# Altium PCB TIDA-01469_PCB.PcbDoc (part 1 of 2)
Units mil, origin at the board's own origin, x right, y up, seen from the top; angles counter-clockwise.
Board outline 2303.15 x 3751.97 mil, 4 copper layers (Layer 1 - Top Layer, Layer 2 - GND, Layer 3 - PWR, Layer 4 - Bottom Layer), stack 61.634 mil thick; 66 components, 33 nets, 183 pads, 184 vias.
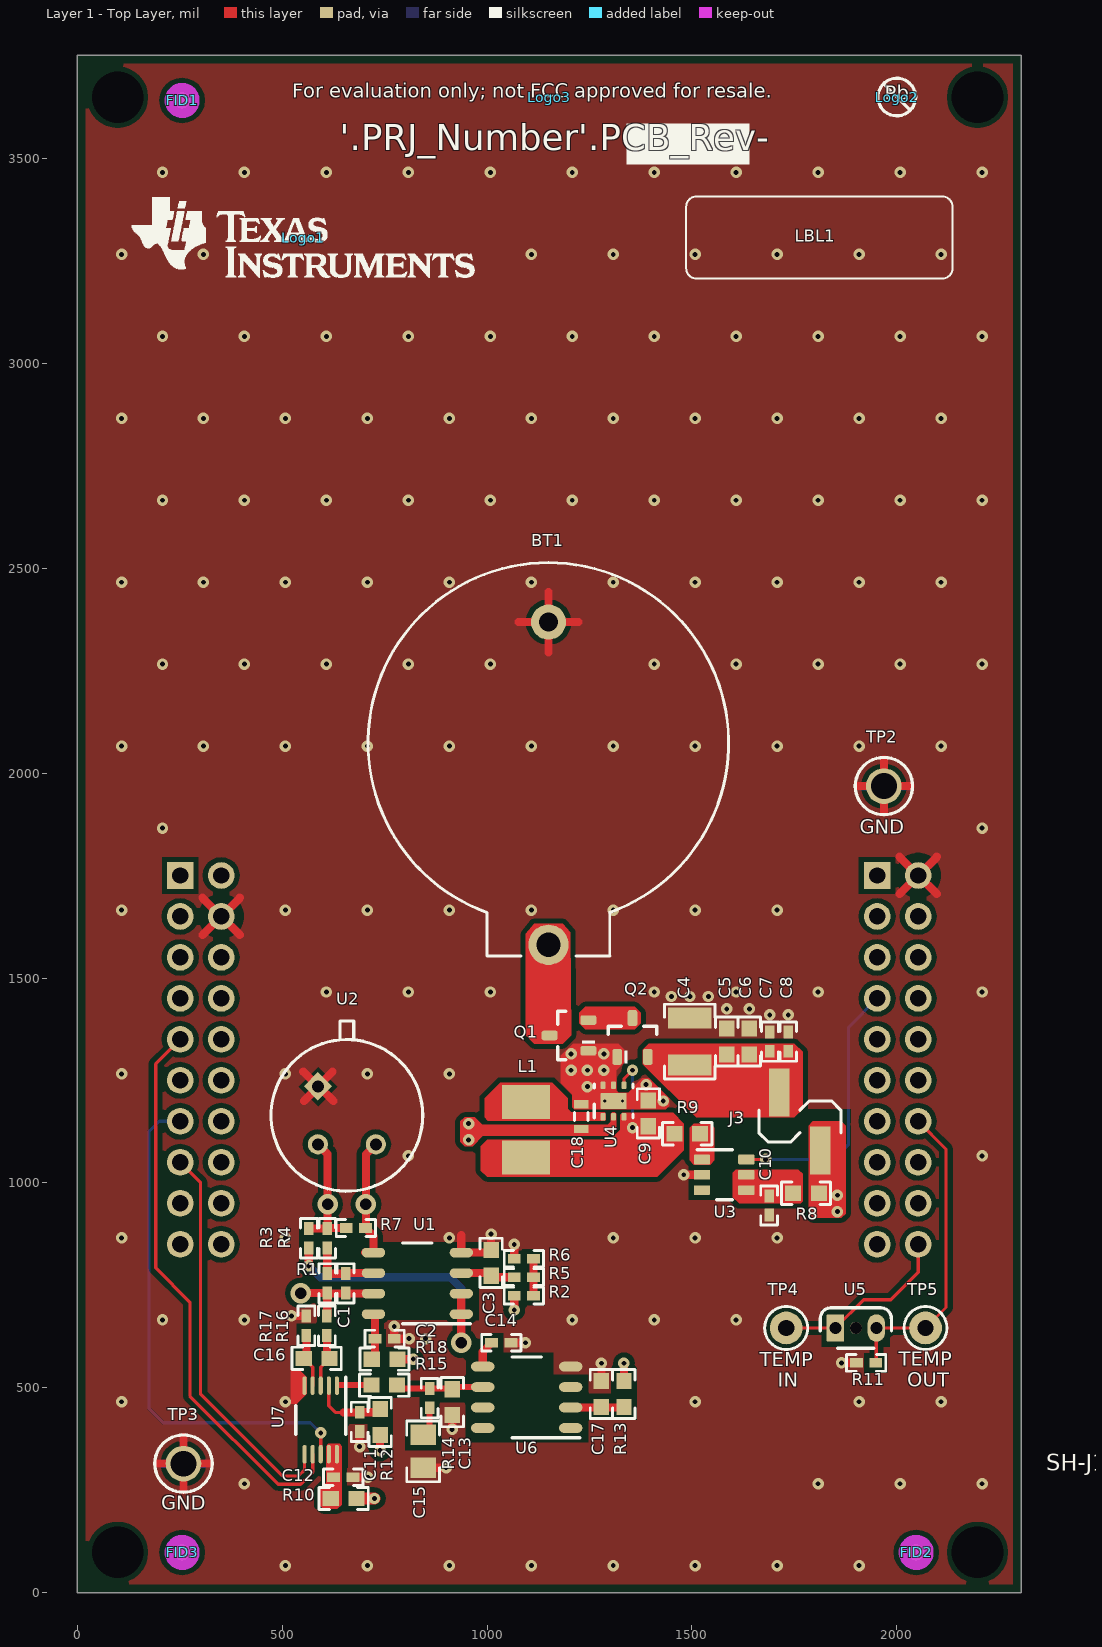
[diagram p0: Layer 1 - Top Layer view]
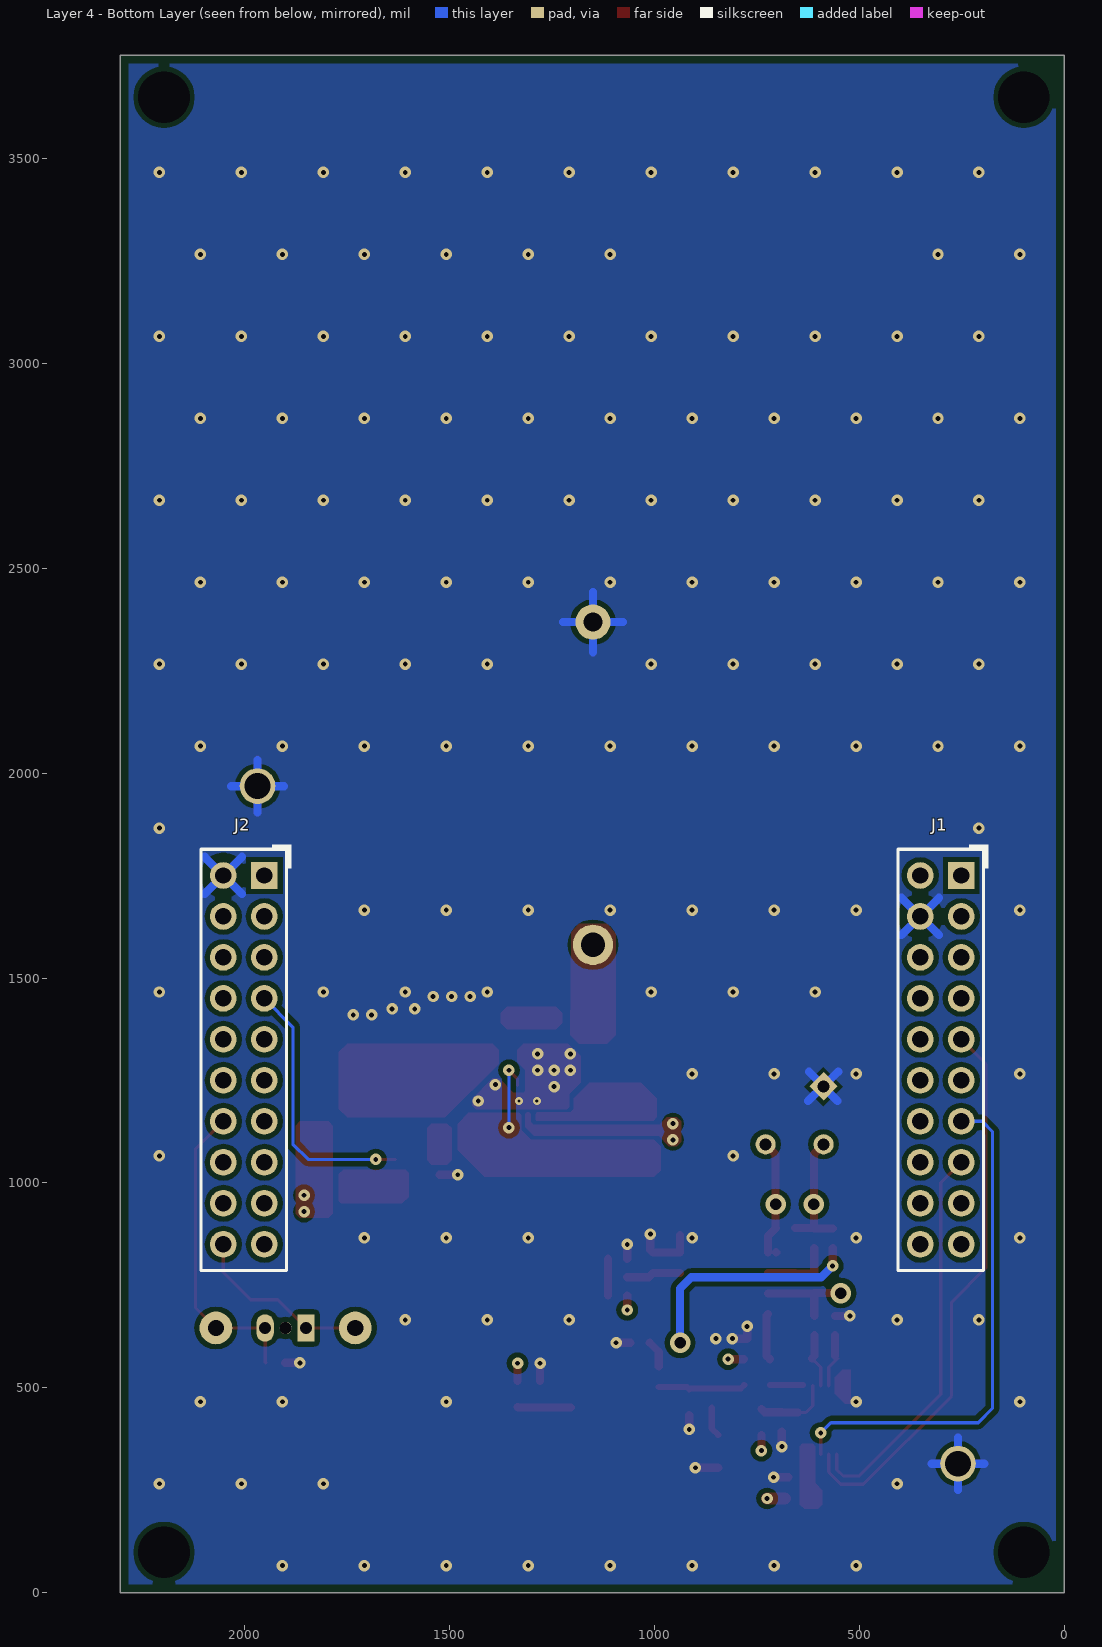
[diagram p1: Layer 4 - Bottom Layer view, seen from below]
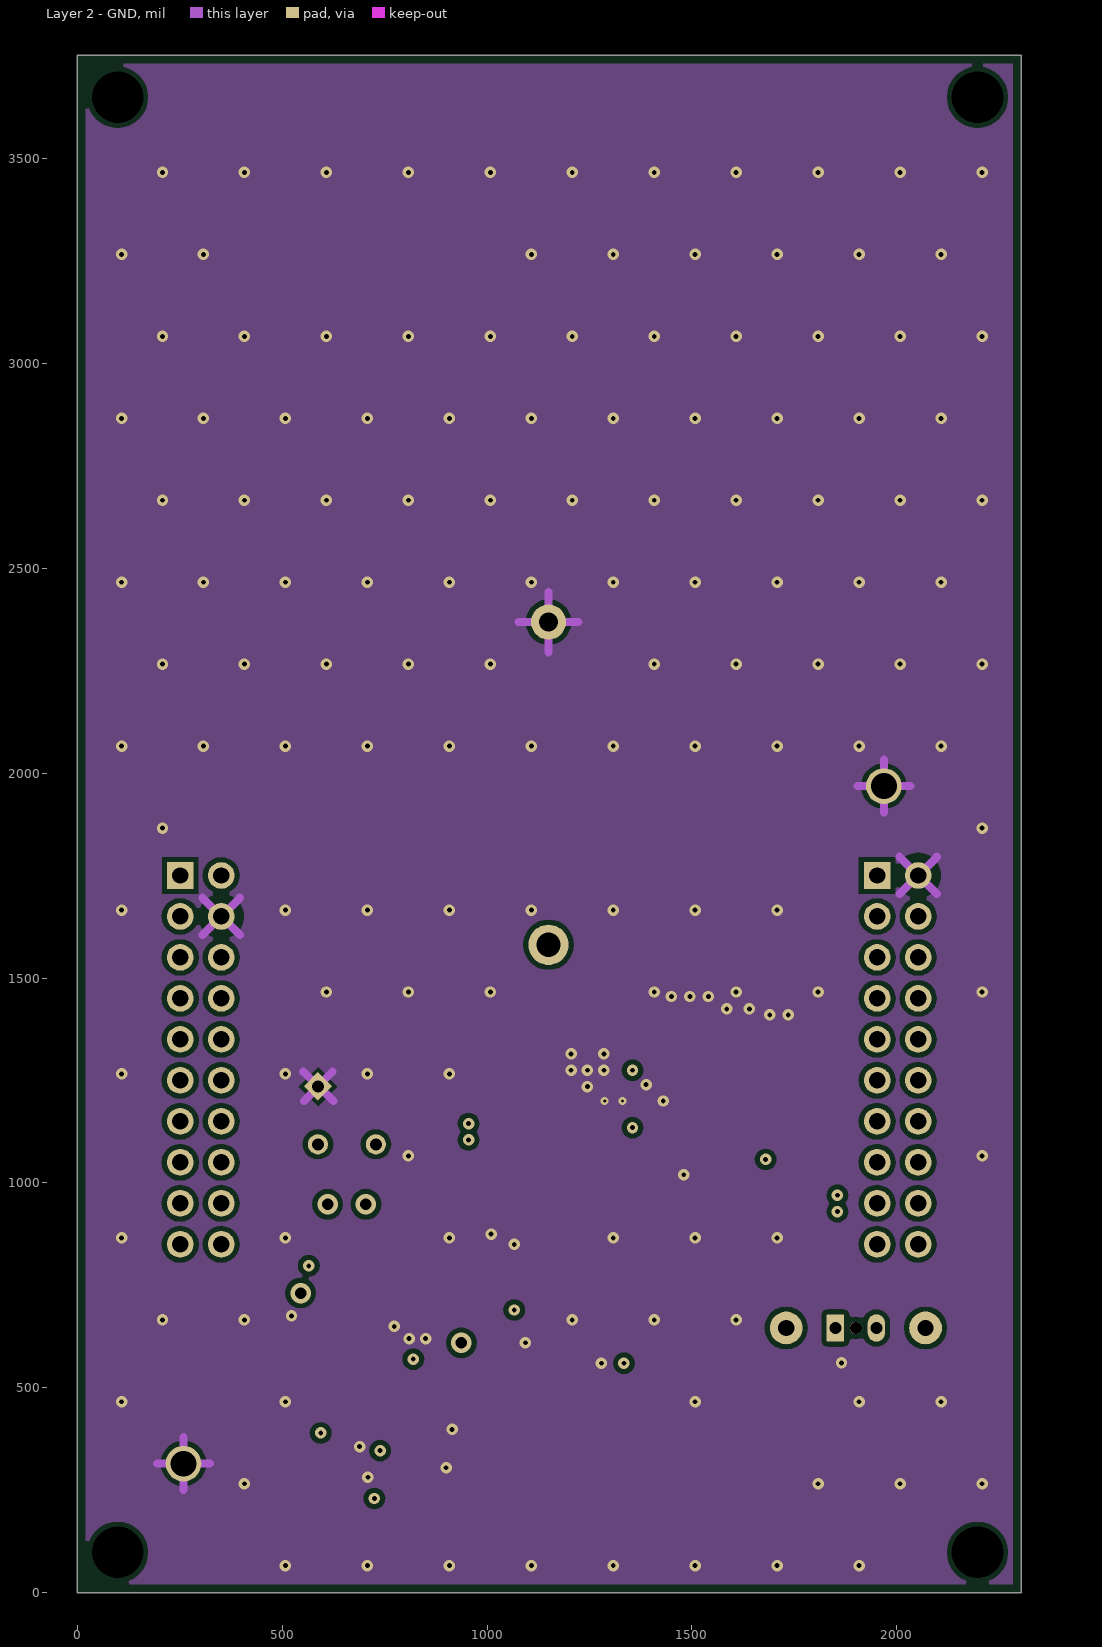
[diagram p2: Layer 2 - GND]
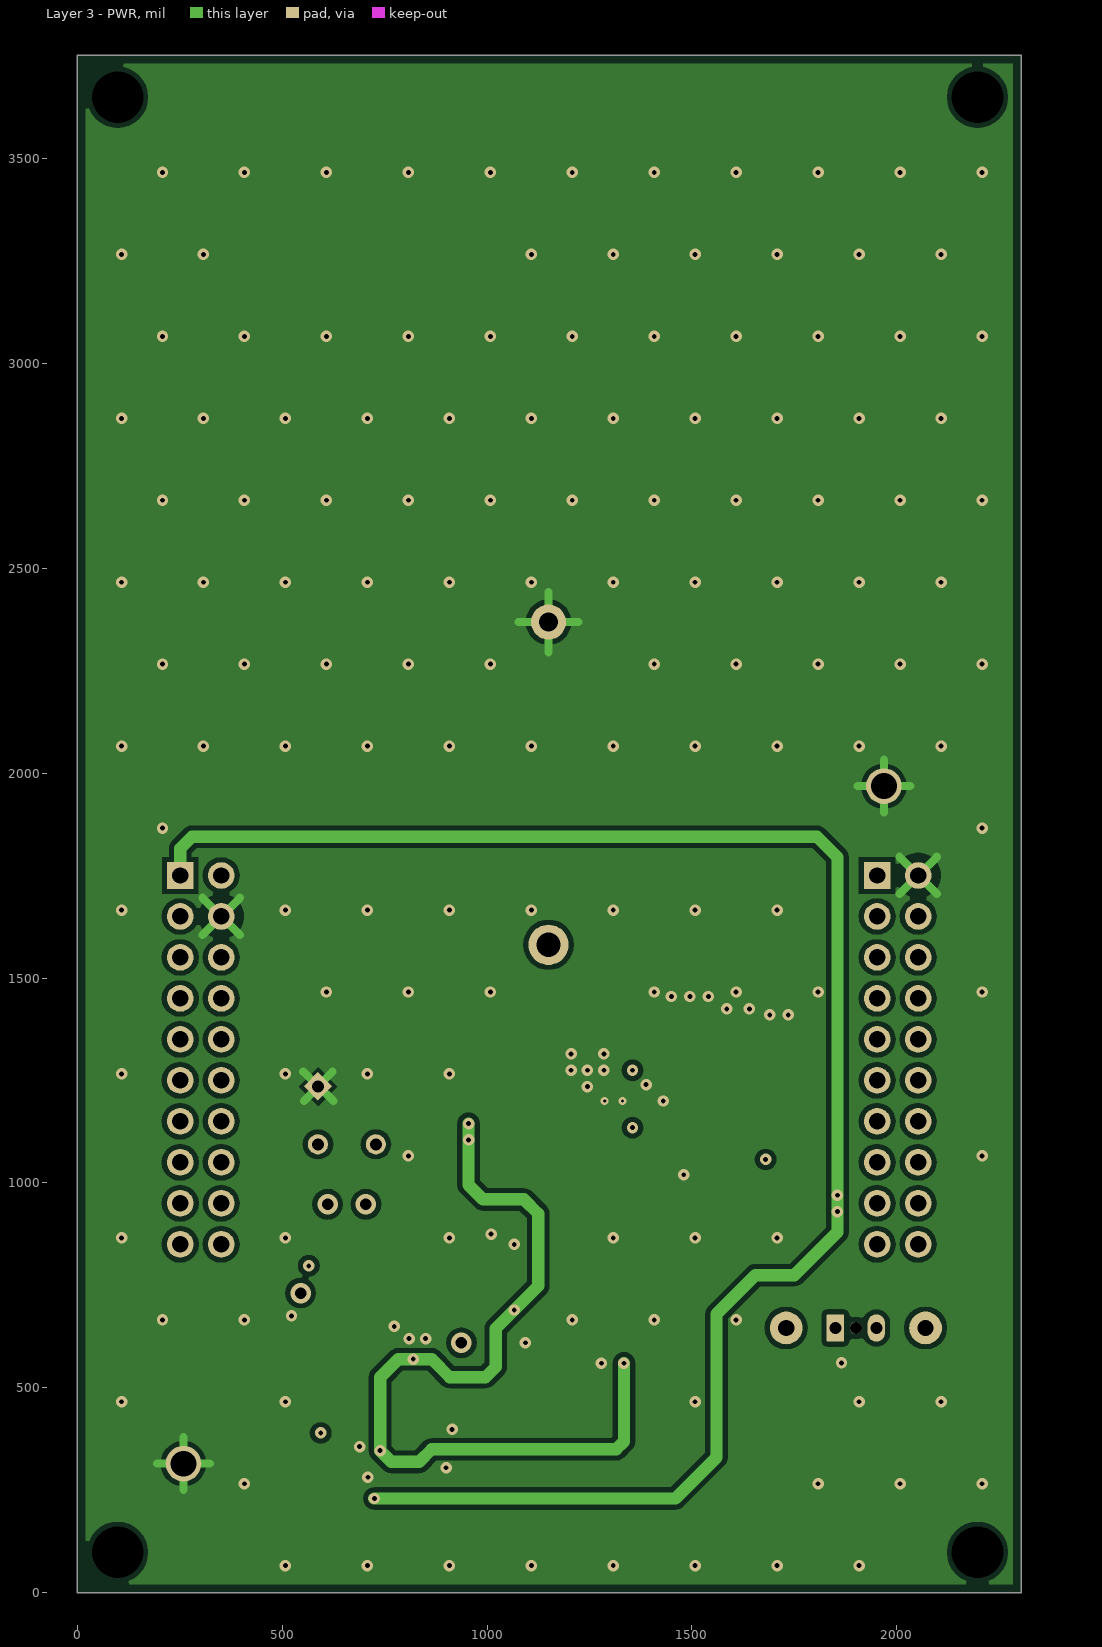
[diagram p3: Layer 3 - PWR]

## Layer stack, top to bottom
Top Solder: solder mask 0.4, Solder Resist, Dk 3.5
Layer 1 - Top Layer: signal copper 1.4
Dielectric 1: prepreg 10, FR-4, Dk 4.2
Layer 2 - GND: signal copper 1.417
Dielectric 2: core 36, FR-4, Dk 4.2
Layer 3 - PWR: signal copper 1.417
Dielectric 3: prepreg 10, FR-4, Dk 4.2
Layer 4 - Bottom Layer: signal copper 1.4
Bottom Solder: solder mask 0.4, Solder Resist, Dk 3.5

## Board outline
0,0 0,3751.97 2303.15,3751.97 2303.15,0

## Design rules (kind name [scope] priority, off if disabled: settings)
AcuteAngle [All] p1: minimum=4.50000000000000E+0001 checktracksonly=FALSE
AssemblyTestPointUsage [All] p1: valid=2
BoardOutlineClearance BoardOutlineClearance_MountingHoles [OnCopper and InComponentClass('Mounting Holes')] p1: gap=40
BoardOutlineClearance BoardOutlineClearance_Poly [OnCopper and IsPoly] p2: gap=20
BoardOutlineClearance [OnCopper and Not InComponentClass('Logo') and not InComponentClass('FiducialMark') and not InRegion(1000,500,4000,800) and not InPoly] p3: gap=20
Clearance Clearance_Keepouts [((IsTrack Or IsArc) And Not InPoly) And IsFree and IsKeepOut vs ((IsTrack Or IsArc) And Not InPoly) And IsFree and IsKeepOut] p1: gap=0
Clearance Clearance_Poly [InPolygon] p2: gap=12
Clearance [All] p3: gap=7.87
ComponentClearance ComponentClearance_MountingHoles_FiducialMarks [InComponentClass('Mounting Holes') vs InComponentClass('FiducialMark')] p1: gap=50 collisioncheckmode=3 verticalgap=10 showdistances=FALSE
ComponentClearance ComponentClearance_Shunt [InComponentClass('Header') vs InComponentClass('Shunt')] p2: gap=0 collisioncheckmode=3 verticalgap=0 showdistances=FALSE
ComponentClearance ComponentClearance_Logo [InComponentClass('Logo')] p3: gap=50 collisioncheckmode=3 verticalgap=10 showdistances=FALSE
ComponentClearance ComponentClearance_ScrewToNut [(HasFootprint('NY PMS 440 0025 PH')) vs (HasFootprint('Keystone_1902C'))] p4: gap=5 collisioncheckmode=3 verticalgap=10 showdistances=FALSE
ComponentClearance ComponentClearance_MountingHoles [InComponentClass('Mounting Holes')] p5: gap=250 collisioncheckmode=3 verticalgap=100000 showdistances=FALSE
ComponentClearance ComponentClearance_SmallPassives [HasFootprint('0201*') or HasFootprint('0402*') or HasFootprint('0508') or HasFootprint('0603*') or HasFootprint('0612') or HasFootprint('0805*') or HasFootprint('0815*') or HasFootprint('0830*') or HasFootprint('1206*') or HasFootprint('1210*') or HasFootprint('1808*') or HasFootprint('1812*') or HasFootprint('1825*') or HasFootprint('2010*') or HasFootprint('2220*') or HasFootprint('2225*') or HasFootprint('2512*') or HasFootprint('2728*') or HasFootprint('3518*') vs HasFootprint('0201*') or HasFootprint('0402*') or HasFootprint('0508') or HasFootprint('0603*') or HasFootprint('0612') or HasFootprint('0805*') or HasFootprint('0815*') or HasFootprint('0830*') or HasFootprint('1206*') or HasFootprint('1210*') or HasFootprint('1808*') or HasFootprint('1812*') or HasFootprint('1825*') or HasFootprint('2010*') or HasFootprint('2220*') or HasFootprint('2225*') or HasFootprint('2512*') or HasFootprint('2728*') or HasFootprint('3518*')] p6: gap=14.96 collisioncheckmode=3 verticalgap=10 showdistances=FALSE
ComponentClearance ComponentClearance_THtoSMT [IsThruComponent vs IsSMTComponent] p7: gap=35 collisioncheckmode=3 verticalgap=30 showdistances=FALSE
ComponentClearance ComponentClearance_THtoTH [IsThruComponent vs IsThruComponent] p8: gap=30 collisioncheckmode=3 verticalgap=30 showdistances=FALSE
ComponentClearance [All] p9: gap=10 collisioncheckmode=3 verticalgap=10 showdistances=FALSE
DiffPairsRouting [All] p1: maxlimit=100 minlimit=10 mostfreqgap=10 toplayer_minwidth=15 toplayer_maxwidth=15 toplayer_prefwidth=15 midlayer1_minwidth=15 midlayer1_maxwidth=15 midlayer1_prefwidth=15 midlayer2_minwidth=15 midlayer2_maxwidth=15 midlayer2_prefwidth=15 bottomlayer_minwidth=15 bottomlayer_maxwidth=15 bottomlayer_prefwidth=15 maxuncoupledlength=1000
FabricationTestPointUsage TestPointUsage [All] p1: valid=2 allowmultiple=FALSE
FabricationTestpoint Testpoint [All] p1: side=3 testpointundercomponent=TRUE minsize=40 maxsize=100 preferedsize=60 minholesize=0 maxholesize=40 preferedholesize=32 testpointgrid=1 allowsidetop=TRUE allowsidebottom=TRUE usegrid=TRUE gridtolerance=0.01
FanoutControl Fanout_LCC [IsLCC] p1: bgadir=Out bgaviamode=Centered fanoutstyle=Auto fanoutdirection=Alternating viagrid=1 // Fanout_LCC (Default Rule)
FanoutControl Fanout_BGA [IsBGA] p2: bgadir=Out bgaviamode=Centered fanoutstyle=Auto fanoutdirection=Alternating viagrid=1 // Fanout_BGA (Default Rule)
FanoutControl Fanout_Default [All] p4: bgadir=Out bgaviamode=Centered fanoutstyle=Auto fanoutdirection=Alternating viagrid=1 // Fanout_Default (Default Rule)
FanoutControl Fanout_Small [(CompPinCount < 5)] p5: bgadir=Out bgaviamode=Centered fanoutstyle=Auto fanoutdirection=OutThenIn viagrid=1 // Fanout_Small (Default Rule)
HoleSize [All] p1: absolutevalues=TRUE maxlimit=251 minlimit=7.87 maxpercent=80.000 minpercent=20.000
MinimumAnnularRing MinimumAnnularRing_ThermalPadVias [IsVia and InAnyComponent] p1: minimumring=5.91
MinimumAnnularRing [All] p2: minimumring=6
MinimumSolderMaskSliver MinimumSolderMaskSliver_Logo [InComponentClass('Logo') vs InComponentClass('Logo')] p1: minsoldermaskwidth=0.7
MinimumSolderMaskSliver [All] p2: minsoldermaskwidth=3.94
NetAntennae [All] p1 off: netantennaetolerance=2000
PlaneConnect [All] p1: planeconnectstyle=Relief reliefexpansion=10 reliefentries=4 reliefconductorwidth=10 reliefairgap=10
PolygonConnect [All] p1: connectstyle=Direct reliefconductorwidth=10 reliefentries=4 polygonreliefangle="90 Angle" airgapwidth=10
RoutingVias ThermalPadVias [IsVia and InAnyComponent] p1: holewidth=7.87 width=19.68 viastyle="Through Hole" minholewidth=7.87 minwidth=19.68 maxholewidth=12.99 maxwidth=23.62
RoutingVias [All] p2: holewidth=16 width=34 viastyle="Through Hole" minholewidth=7.87 minwidth=26 maxholewidth=40 maxwidth=65
SilkToBoardRegionClearance [Not ((IsComment or IsDesignator) And (Hide <> 'False')) and not InRegion(1000,500,4000,800)] p1:
SilkToSilkClearance SilkToSilkClearance_Pb-FreeLogo [(HasFootprint('Pb-Free_Overlay_Medium') OR HasFootprint('Pb-Free_Overlay_Small')) vs (HasFootprint('Pb-Free_Overlay_Medium') OR HasFootprint('Pb-Free_Overlay_Small'))] p1: silktosilkclearance=0
SilkToSilkClearance [All] p2: silktosilkclearance=4
SilkToSolderMaskClearance SilkToComponentPadClearance [(IsPad or IsFill or IsRegion) and InAnycomponent] p1: minsilkscreentomaskgap=3.9 clearancetoexposedcopper=TRUE
SilkToSolderMaskClearance "Silk to Solder Mask Opening" [All] p2: minsilkscreentomaskgap=3.6 clearancetoexposedcopper=FALSE
SolderMaskExpansion [All] p1: expansion=1.97
Width [All] p1: maxlimit=100 minlimit=6 preferedwidth=10 checkconnectedcopper=TRUE
14 further rules are at their usual default settings.

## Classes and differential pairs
component class Shunt: SH-J1
component class Label: LBL1
component class AssemblyNote: ZZ1 ZZ2 ZZ3 ZZ4
component class FiducialMark: FID1 FID2 FID3
component class TIDA-01469_EVM_Hardware: FID1 FID2 FID3 LBL1 Logo1 Logo2 Logo3 SH-J1 ZZ1 ZZ2 ZZ3 ZZ4
component class Logo: Logo1
component class Header: J3
component class TIDA-01469_Main: BT1 C4 C5 C6 C7 C8 C9 C10 C11 C12 C13 C14 C15 C16 C17 C18 J1 J2 J3 L1 Q1 Q2 R8 R9 R10 R11 R12 R13 R14 R15 R16 R17 TP2 TP3 TP4 TP5 U3 U4 U5 U6 U7
component class TIDA-01469_Piezo_Sensor: C1 C2 C3 R1 R2 R3 R4 R5 R6 R7 R18 U1 U2

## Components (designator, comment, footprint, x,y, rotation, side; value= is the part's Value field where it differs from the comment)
BT1 "BS-7" BAT_BS-7 1150,1975 r90 top locked
C1 "0402YC132KAT2A" 0402 655,755 r90 top
C2 "0402YC104KAT2A" 0402 750,620 r180 top
C3 "UMK107AB7105KA-T" 0603 1010,805 r90 top
C4 "GRM32ER60G337ME05L" 1210 1495,1345 r90 top
C5 "C1608X5R0J106M" 0603 1585,1345 r90 top
C6 "C1608X7R1C105K" 0603 1640,1345 r90 top
C7 "C1005X7R1H104K050BB" 0402 1690,1345 r90 top
C8 "C1005X7R1C103K050BA" 0402 1735,1345 r90 top
C9 "C0603C106M9PACTU" 0603 1393.68,1170 r90 top
C10 "C1005X7S1A105K050BC" 0402 1688.56,945 r270 top
C11 "C1005X7S1A105K050BC" 0402 689.09,416.77 r270 top
C12 "C1005X7S1A105K050BC" 0402 649.17,281.77 r0 top
C13 "C0603C106M9PACTU" 0603 915,465 r270 top
C14 "C1005X7S1A105K050BC" 0402 1035,610 r0 top
C15 "C2012X5R1A476M125AC" 0805_HV 844.17,344.96 r270 top
C16 "06031C102JAT2A" 0603 584.17,571.77 r180 top
C17 "06033C105KAT2A" 0603 1279.09,484.96 r90 top
C18 "C1608X5R0G226M080AA" 0603S 1230,1162 r90 top
FID1 "Fiducial" Fiducial10-20 255.91,3641.73 r0 top
FID2 "Fiducial" Fiducial10-20 2047.24,98.43 r0 top
FID3 "Fiducial" Fiducial10-20 255.91,98.43 r0 top
J1 "PPPC102LFBN-RC" Sullins_PPPC102LFBN-RC 301.3,1300.39 r90 bottom locked
J2 "PPPC102LFBN-RC" Sullins_PPPC102LFBN-RC 2002.09,1300.39 r90 bottom locked
J3 "0878980204" Molex_87898-0204 1763.56,1150 r0 top
L1 "VLCF5024T-330MR50-2" VLCF5024 1095,1130 r90 top
LBL1 "Size: 0.65\" x 0.20 \"" Label_650x200 1811.02,3307.09 r0 top
Logo1 "Texas Instruments" TI_Stacked_Overlay_Small 551.18,3307.09 r0 top
Logo2 "Pb-Free Symbol" Pb-Free_Overlay_Small 2000,3650 r0 top
Logo3 "FCC disclaimer" FCC_disclaimer 1151.57,3650 r0 top
Q1 "SI2323DS" SOT-23 1200,1360 r180 top
Q2 "SI2323DS" SOT-23 1355,1355 r90 top
R1 "CRCW040210K0FKED" 0402 610,755 r270 top
R2 "CRCW0402100KFKED" 0402 1090,725 r180 top
R3 "CRCW04020000Z0ED" 0402 565,865 r90 top
R4 "CRCW0402100RFKED" 0402 610,865 r270 top
R5 "CRCW0402100KFKED" 0402 1090,770 r180 top
R6 "CRCW040276K8FKED" 0402 1090,815 r0 top
R7 "CRCW040210M0FKED" 0402 680,890 r0 top
R8 "RMCF0603ZT0R00" 0603 1778.56,975 r180 top
R9 "RMCF0603ZT0R00" 0603 1488.56,1120 r180 top
R10 "RMCF0603ZT0R00" 0603 650,230 r0 top
R11 "CRCW040218K0FKED" 0402 1925.01,561.07 r0 top
R12 "RMCF0603ZT0R00" 0603 739.09,416.77 r270 top
R13 "RMCF0603ZT0R00" 0603 1334.09,484.96 r270 top
R14 "CRCW04021R21FKED" 0402 860,475 r90 top
R15 "RMCF0603ZT0R00" 0603 749.17,506.77 r180 top
R16 "CRCW040221R5FKED" 0402 609.17,651.77 r270 top
R17 "CRCW040221R5FKED" 0402 559.17,651.77 r270 top
R18 "RMCF0603ZT0R00" 0603 750,570 r0 top
SH-J1 "969102-0000-DA" SNT-100-BK-G 2408,171 r90 top
TP2 "5011" Keystone5011 1968.5,1968.5 r0 top
TP3 "5011" Keystone5011 259.15,315 r0 top
TP4 "5004" Keystone5004 1730.01,646.07 r90 top
TP5 "5004" Keystone5004 2070.01,646.07 r90 top
U1 "OPA2325IDR" D0008A_N 830,755 r180 top
U2 "66192CPZ1" TO-5-3 658,1165 r90 top
U3 "TPS22860DBVR" DBV0006A_N 1578.56,1020 r0 top
U4 "TPS61291DRVR" DRV0006A 1308.68,1200 r90 top
U5 "LMT01LPG" LPG0002A 1900.01,646.07 r0 top
U6 "REF5030AIDG4" D0008A_N 1096.81,476.93 r180 top
U7 "ADS8866IDGSR" DGS0010A_L 594.17,421.77 r270 top
ZZ1 "This Assembly Note is for PCB labels only" AssemblyNoteLabel 200,4200 r0 top
ZZ2 "These assemblies are ESD sensitive, ESD precautions shall be observed." AssemblyNote 200,4100 r0 top
ZZ3 "These assemblies must be clean and free from flux and all contaminants. Use of no clean flux is not acceptable." AssemblyNote 200,4000 r0 top
ZZ4 "These assemblies must comply with workmanship standards IPC-A-610 Class 2, unless otherwise specified." AssemblyNote 200,3900 r0 top

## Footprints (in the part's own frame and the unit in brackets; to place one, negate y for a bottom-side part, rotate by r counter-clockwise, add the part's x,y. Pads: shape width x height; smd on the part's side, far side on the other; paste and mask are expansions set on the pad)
0402 [mm] "0402 from SM-752 data"
  rect 0.8x0.6 smd: 1(-0.6,0) 2(0.6,0)
  silkscreen extent -1.22,-0.52 1.22,0.52, body extent -0.55,-0.3 0.55,0.3, height 0.6
0603 [mm] "0603 from SM-752 data"
  rect 1x0.95 smd: 1(-0.8,0) 2(0.8,0)
  silkscreen extent -1.52,-0.69 1.52,0.69, body extent -0.87,-0.47 0.87,0.47, height 1
0603S [mil]
  rect 20x35 smd: 1(-30,0) 2(30,0)
  silkscreen extent -10,-17 10,17, body extent -34,-19 34,19, height 39
0805_HV [mil] "0805 with 30mil clearance between pads"
  rect 50x63 smd: 1(-40,0) 2(40,0)
  silkscreen extent -74,-40 74,40, body extent -43,-29 43,29, height 57
1210 [mm] "1210 from SM-752 data"
  rect 1.3x2.7 smd: 1(-1.45,0) 2(1.45,0)
  silkscreen extent -2.32,-1.57 2.32,1.57, body extent -1.7,-1.35 1.7,1.35, height 1.35
AssemblyNote [mil] "Assembly Note"
AssemblyNoteLabel [mil] "Assembly Note for PCB Labels"
BAT_BS-7 [mm] "Memory Protection Devices CR2032 battery holder"
  round 2.5 hole 1.5: 1(-10,0)
  round 2.17 hole 1.181: 2(10,0)
  silkscreen extent -10.7,-11.16 13.68,11.18, body extent -10.69,-11.16 13.7,11.16, height 9.02
D0008A_N [mm] "SOIC, 8-Leads, Body 4.9x3.9mm, Pitch 1.27mm, IPC Medium Density"
  oval 1.45x0.6 smd: 1(-2.725,1.905) 2(-2.725,0.635) 3(-2.725,-0.635) 4(-2.725,-1.905) 5(2.725,-1.905) 6(2.725,-0.635) 7(2.725,0.635) 8(2.725,1.905)
  silkscreen extent -3.3,-2.5 0.9,2.5, body extent -3,-2.45 3,2.45, height 1.63
DBV0006A_N [mm] "SOT23, 6-Leads, Body 2.9x1.6mm, Pitch 0.95mm, Lead Span 2.8mm, IPC Medium Density"
  rrect17% 1x0.6 smd: 1(-1.375,0.95) 2(-1.375,0) 3(-1.375,-0.95) 4(1.375,-0.95) 5(1.375,0) 6(1.375,0.95)
  silkscreen extent -1.68,-1.55 0.5,1.55, body extent -1.42,-1.46 1.42,1.46, height 1.12
DGS0010A_L [mm] "TSSOP, 10-Leads, Body 3x3mm, Pitch 0.5mm, IPC High Density"
  oval 1.15x0.25 smd: 1(-2.125,1) 2(-2.125,0.5) 3(-2.125,0) 4(-2.125,-0.5) 5(-2.125,-1) 6(2.125,-1) 7(2.125,-0.5) 8(2.125,0) 9(2.125,0.5) 10(2.125,1)
  silkscreen extent -2.65,-1.55 0.9,1.55, body extent -2.45,-1.5 2.45,1.5, height 0.96
DRV0006A [mm] "SON, 6-Leads, Body 2x2mm, Pitch 0.65mm, Thermal Pad 1.6x1mm, TI Recommended"
  rrect33% 0.45x0.3 smd: 1(-0.975,0.65) 2(-0.975,0) 3(-0.975,-0.65) 4(0.975,-0.65) 5(0.975,0) 6(0.975,0.65)
  rrect14% 1x0.7 on Top Paste: 7(0,0.45) 7(0,-0.45)
  rrect10% 1x1.6 smd paste-0.5: 7(0,0)
  silkscreen extent -1.05,-1.2 1.05,1.2, body extent -1.05,-1.05 1.05,1.05, height 0.81
FCC_disclaimer [mil]
Fiducial10-20 [mm]
  round 1 smd mask+0.5: 1(0,0)
  Layer 1 - Top Layer keep-out circle w1.178: c0,0 r0.5
Keystone5004 [mil] "For Keystone 500x miniature loop terminals"
  round 80 hole 40: 1(0,0)
  silkscreen extent -52,-52 52,52, body extent -49,-49 49,49, height 182
Keystone5011 [mil] "Keystone Multipurpose loops"
  round 87 hole 63: 1(0,0)
  silkscreen extent -70,-70 70,70, body extent -63,-63 63,62, height 319
Label_650x200 [mil] "Thermal Transfer Label"
  silkscreen extent -325,-100 325,100, body extent -325,-100 325,100, height 1
LPG0002A [mm] "TO, 2-Leads, Body 4x1.52mm"
  rrect9% 1.07x1.7 hole 0.75: 1(-1.27,0)
  rrect100% 1.07x1.7 hole 0.75: 2(1.27,0)
  round 0.75 hole 0.75 unplated paste+0 mask+0: MH(0,0)
  silkscreen extent -2.21,-1.25 2.21,1.25, body extent -2,-0.98 2,0.54, height 5.06
Molex_87898-0204 [mm] "Header, 2.54 mm, 2x1, R/A, SMT"
  rect 1.27x2.96 smd: 1(-1.27,1.8) 2(1.27,-1.8)
  silkscreen extent -2.54,-1.27 2.54,1.27, body extent -2.54,-2.4 2.54,2.4, height 9.65
Pb-Free_Overlay_Small [mil]
  silkscreen extent -46,-46 46,46
SNT-100-BK-G [mil] "Samtec STEP model"
  round 1 on Mech3: 0(0,0)
  body extent -100,-50 100,50, height 344
SOT-23 [mm] "SOT23, 3-Leads, Body 2.9x1.3mm, Pitch 0.95mm, Lead Span 2.5mm, IPC Medium Density"
  rrect50% 1x0.6 smd: 1(-1.2,0.95) 2(-1.2,-0.95) 3(1.2,0)
  silkscreen extent -1.63,-1.5 0.7,1.5, body extent -1.16,-1.45 1.21,1.45, height 1
Sullins_PPPC102LFBN-RC [mil] "Sullins"
  rect 65x65 hole 40: 1(450,-50)
  round 65 hole 40: 2(450,50) 3(350,-50) 4(350,50) 5(250,-50) 6(250,50) 7(150,-50) 8(150,50) 9(50,-50) 10(50,50) 11(-50,-50) 12(-50,50) 13(-150,-50) 14(-150,50) 15(-250,-50) 16(-250,50) 17(-350,-50) 18(-350,50) 19(-450,-50) 20(-450,50)
  silkscreen extent -514,-116 526,104, body extent -514,-104 514,104, height 335
TI_Stacked_Overlay_Small [mil]
  silkscreen extent -418,-98 418,98
TO-5-3 [mm] "Standard TO-5, 3-Leads, Height 6.6mm"
  rect 1.25x1.25 hole 0.75 rot 135: 1(1.796,1.796)
  round 1.25 hole 0.75: 2(-1.796,1.796) 3(-1.796,-1.796)
  silkscreen extent -4.7,-4.7 5.84,4.7, body extent -4.7,-4.69 5.84,4.69, height 6.7
VLCF5024 [mm] "TDK"
  rect 2.1x3 smd: 1(-1.725,0) 2(1.725,0)
  Layer 1 - Top Layer region: -0.675,2.45 -1.875,2.45 -2.775,1.55 -2.775,1.4 -0.675,1.4
  Layer 1 - Top Layer region: -0.675,-2.45 -1.875,-2.45 -2.775,-1.55 -2.775,-1.4 -0.675,-1.4
  Layer 1 - Top Layer region: 0.675,-2.45 1.875,-2.45 2.775,-1.55 2.775,-1.4 0.675,-1.4
  Layer 1 - Top Layer region: 0.675,2.4 1.875,2.4 2.775,1.5 2.775,1.35 0.675,1.35
  body extent -2.6,-2.6 2.6,2.6, height 2.4

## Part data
BT1: "Battery Holder, CR2032, Retainer clip, TH"
C1: "CAP, CERM, 1300 pF, 16 V, +/- 10%, X7R, 0402"
C2: "CAP, CERM, 0.1 µF, 16 V, +/- 10%, X7R, 0402"
C3: "CAP, CERM, 1 µF, 50 V, +/- 10%, X7R, 0603"
C4: library part Capacitor, "CAP, CERM, 330 µF, 4 V, X5R, +/- 20%, 1210"
C5 C9 C13: "CAP, CERM, 10 µF, 6.3 V, +/- 20%, X5R, 0603"
C6: "CAP, CERM, 1 µF, 16 V, +/- 10%, X7R, 0603"
C7: "CAP, CERM, 0.1 µF, 50 V, +/- 10%, X7R, 0402"
C8: "CAP, CERM, 0.01 µF, 16 V, +/- 10%, X7R, 0402"
C10 C11 C12 C14: "CAP, CERM, 1 µF, 10 V, +/- 10%, X7S, 0402"
C15: "CAP, CERM, 47 µF, 10 V, +/- 20%, X5R, 0805"
C16: "CAP, CERM, 1000 pF, 100 V, +/- 5%, X7R, 0603"
C17: "CAP, CERM, 1 µF, 25 V, +/- 10%, X7R, 0603"
C18: "CAP, CERM, 22 µF, 4 V, +/- 20%, X5R, 0603"
FID1 FID2 FID3: "Fiducial mark.  There is nothing to buy or mount."
J1 J2: "Receptacle, 100mil, 10x2, Gold, TH"
J3: "Header, 2.54 mm, 2x1, Gold, R/A, SMT"
L1: "Inductor, Shielded, Ferrite, 0.5 A, 0.275 ohm, SMD"
LBL1: library part THT-14-423-10, "Thermal Transfer Printable Labels, 0.650\" W x 0.200\" H - 10,000 per roll"
Logo1: library part TI_Logo, "Texas Instrument Corporate Signature"
Logo2: library part Pb-Free
Logo3: library part FCC_disclaimer, "FCC_disclaimer"
Q1 Q2: "MOSFET, P-CH, -20 V, -3.7 A, SOT-23"
R1: "RES, 10.0 k, 1%, 0.063 W, 0402"
R2 R5: "RES, 100 k, 1%, 0.063 W, 0402"
R3: "RES, 0, 5%, 0.063 W, 0402"
R4: "RES, 100, 1%, 0.063 W, 0402"
R6: "RES, 76.8 k, 1%, 0.063 W, 0402"
R7: "RES, 10.0 M, 1%, 0.063 W, 0402"
R8 R9 R10 R12 R13 R15 R18: "RES, 0, 1%, 0.1 W, AEC-Q200 Grade 0, 0603"
R11: "RES, 18.0 k, 1%, 0.063 W, AEC-Q200 Grade 0, 0402"
R14: "RES, 1.21, 1%, 0.063 W, 0402"
R16 R17: "RES, 21.5, 1%, 0.063 W, 0402"
SH-J1: "Shunt, 100mil, Gold plated, Black"
TP2 TP3: "Test Point, Multipurpose, Black, TH"
TP4 TP5: "Test Point, Miniature, Yellow, TH"
U1: "Precision, 10-MHz, Low-Noise, Low-Power, RRIO, CMOS Zero-Crossover Operational Amplifier, D0008A (SOIC-8)"
U2: "Accelerometer, 350 pF, 10 kHz, TH"
U3: "TPS22860 Ultra-low leakage load switch, DBV0006A (SOT-23-6)"
U4: "LOW Iq BOOST CONVERTER WITH BYPASS OPERATION, DRV0006A (WSON-6)"
U5: "0.5degC Accurate 2-pin Temperature Sensor with a Pulse Train Interface, LPG0002A (TO-92-2)"
U6: "Low Noise, Very Low Drift, Precision Voltage Reference, -40 to 125 degC, 8-pin SOIC (D), Green (RoHS & no Sb/Br)"
U7: "16-Bit, 100-kSPS, Serial Interface, microPower, Miniature, Single-Ended Input, SAR Analog-to-Digital, DGS0010A (VSSOP-10)"
ZZ1: library part AssemblyNoteLabel
ZZ2 ZZ3 ZZ4: library part AssemblyNote

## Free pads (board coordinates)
  round 0 hole 125.98 unplated: ""(98.43,98.43) ""(98.43,3649.61) ""(2196.85,98.43) ""(2196.85,3649.61)

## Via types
v1: diameter 28, hole 12, Layer 1 - Top Layer to Layer 4 - Bottom Layer, tented both sides, 178 vias
v2: diameter 50, hole 28, Layer 1 - Top Layer to Layer 4 - Bottom Layer, 4 vias
v3: diameter 19.68, hole 7.87, Layer 1 - Top Layer to Layer 4 - Bottom Layer, 2 vias

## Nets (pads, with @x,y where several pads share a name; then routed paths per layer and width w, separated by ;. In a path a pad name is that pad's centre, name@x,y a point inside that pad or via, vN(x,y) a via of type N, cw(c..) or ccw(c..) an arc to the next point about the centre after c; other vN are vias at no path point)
GND: BT1.2 C2.1 C3.2 C4.2 C5.2 C6.2 C7.2 C8.2 C9.2 C10.2 C11.2 C12.2 C13.2 C14.2 C15.2 C17.2 C18.2 J1.4 J2.2 Q1.1 Q2.1 R6.1 R11.1 R17.1 TP2.1 TP3.1 U1.4 U2.1 U3.2 U4.5 U4.6 U4.7@1308.68,1200 U6.4 U7.5 | length 6711.6
  Layer 1 - Top Layer w20: 195.13,315.5 TP3.1@259.29,315.5 ; 259.29,251.35 TP3.1@259.29,315.5 ; 259.29,379.66 TP3.1@259.29,315.5 ; 305.84,1604.94 J1.4@351.3,1650.39 ; 305.85,1695.85 J1.4@351.3,1650.39 ; 323.44,315.5 TP3.1@259.29,315.5 ; 396.75,1604.94 J1.4@351.3,1650.39 ; 396.75,1695.85 J1.4@351.3,1650.39 ; v1(522.8,675.39) R17.1@559.17,675.39 ; 551.58,1271.41 U2.1@587.29,1235.71 ; 553.58,1200 U2.1@589.29,1235.71 ; 623,1271.42 U2.1@587.29,1235.71 ; 625,1200 U2.1@589.29,1235.71 ; C12.2@672.8,281.77 v1(709.17,281.77) ; v1(689.09,356.77) C11.2@689.09,393.15 ; v1(773.62,650) C2.1@773.62,620 v1(810,620) ; C15.2@844.17,304.96 C15.2@844.17,304.96 v1(900,305) ; v1(915,398.5) C13.2@915,433.5 ; 937.28,872.28 U1.4@937.28,830 1003.5,830 C3.2@1010,836.5 v1(1010,875) ; C14.2@1058.62,610 v1(1093.62,610) ; R6.1@1066.38,815 v1(1066.38,850) ; 1076.57,2368.7 BT1.2@1150,2368.7 ; 1150,2295.28 BT1.2@1150,2368.7 ; 1150,2442.13 BT1.2@1150,2368.7 ; 1223.43,2368.7 BT1.2@1150,2368.7 ; C17.2@1279.09,516.46 v1(1279.09,560) ; v1(1480,1020) U3.2@1524.43,1020 ; v1(1865.01,561.07) R11.1@1901.38,561.07 ; 1904.35,1968.5 TP2.1@1968.5,1968.5 ; 1968.5,1904.35 TP2.1@1968.5,1968.5 ; 1968.5,2032.66 TP2.1@1968.5,1968.5 ; 2006.63,1704.94 J2.2@2052.09,1750.39 ; 2006.64,1795.85 J2.2@2052.09,1750.39 ; 2032.66,1968.5 TP2.1@1968.5,1968.5 ; 2097.54,1704.94 J2.2@2052.09,1750.39 ; 2097.54,1795.85 J2.2@2052.09,1750.39 ; U2.1@587.29,1235.71 U2.1@589.29,1235.71
  Layer 2 - GND w20: 195.13,315.5 TP3.1@259.29,315.5 ; 259.29,251.35 TP3.1@259.29,315.5 ; 259.29,379.66 TP3.1@259.29,315.5 ; 305.85,1604.95 J1.4@351.3,1650.39 ; 305.86,1695.86 J1.4@351.3,1650.39 ; 323.44,315.5 TP3.1@259.29,315.5 ; 396.76,1604.95 J1.4@351.3,1650.39 ; 396.76,1695.85 J1.4@351.3,1650.39 ; 551.58,1271.41 U2.1@587.29,1235.71 623,1271.42 ; 553.58,1200 589.29,1235.71 625,1200 ; 1076.57,2368.7 BT1.2@1150,2368.7 ; 1150,2295.28 BT1.2@1150,2368.7 ; 1150,2442.13 BT1.2@1150,2368.7 ; 1223.43,2368.7 BT1.2@1150,2368.7 ; 1904.35,1968.5 TP2.1@1968.5,1968.5 ; 1968.5,1904.35 TP2.1@1968.5,1968.5 ; 1968.5,2032.66 TP2.1@1968.5,1968.5 ; 2006.64,1704.95 J2.2@2052.09,1750.39 ; 2006.64,1795.86 J2.2@2052.09,1750.39 ; 2032.66,1968.5 TP2.1@1968.5,1968.5 ; 2097.55,1704.95 J2.2@2052.09,1750.39 ; 2097.55,1795.85 J2.2@2052.09,1750.39
  Layer 3 - PWR w20: 195.13,315.5 TP3.1@259.29,315.5 ; 259.29,251.35 TP3.1@259.29,315.5 ; 259.29,379.66 TP3.1@259.29,315.5 ; 305.85,1604.95 J1.4@351.3,1650.39 ; 305.85,1695.85 J1.4@351.3,1650.39 ; 323.44,315.5 TP3.1@259.29,315.5 ; 396.75,1604.95 J1.4@351.3,1650.39 ; 396.75,1695.85 J1.4@351.3,1650.39 ; 551.58,1271.41 U2.1@587.29,1235.71 623,1271.42 ; 553.58,1200 589.29,1235.71 625,1200 ; 1076.57,2368.7 BT1.2@1150,2368.7 ; 1150,2295.28 BT1.2@1150,2368.7 ; 1150,2442.13 BT1.2@1150,2368.7 ; 1223.43,2368.7 BT1.2@1150,2368.7 ; 1904.35,1968.5 TP2.1@1968.5,1968.5 ; 1968.5,1904.35 TP2.1@1968.5,1968.5 ; 1968.5,2032.66 TP2.1@1968.5,1968.5 ; 2006.63,1704.95 J2.2@2052.09,1750.39 ; 2006.64,1795.85 J2.2@2052.09,1750.39 ; 2032.66,1968.5 TP2.1@1968.5,1968.5 ; 2097.54,1704.95 J2.2@2052.09,1750.39 ; 2097.54,1795.85 J2.2@2052.09,1750.39
  Layer 4 - Bottom Layer w20: 195,315 TP3.1@259.15,315 ; 259.15,250.85 TP3.1@259.15,315 ; 259.15,379.15 TP3.1@259.15,315 ; 305.84,1604.94 J1.4@351.3,1650.39 ; 305.85,1695.85 J1.4@351.3,1650.39 ; 323.31,315 TP3.1@259.15,315 ; 396.75,1604.94 J1.4@351.3,1650.39 ; 396.75,1695.85 J1.4@351.3,1650.39 ; 551.58,1271.41 U2.1@587.29,1235.71 623,1271.42 ; 553.58,1200 589.29,1235.71 625,1200 ; 1076.57,2368.7 BT1.2@1150,2368.7 ; 1150,2295.28 BT1.2@1150,2368.7 ; 1150,2442.13 BT1.2@1150,2368.7 ; 1223.43,2368.7 BT1.2@1150,2368.7 ; 1904.22,1968 TP2.1@1968.37,1968 ; 1968.37,1903.85 TP2.1@1968.37,1968 ; 1968.37,2032.15 TP2.1@1968.37,1968 ; 2006.63,1704.94 J2.2@2052.09,1750.39 ; 2006.64,1795.85 J2.2@2052.09,1750.39 ; 2032.53,1968 TP2.1@1968.37,1968 ; 2097.54,1704.94 J2.2@2052.09,1750.39 ; 2097.54,1795.85 J2.2@2052.09,1750.39
  other v1: 508,66 708,66 908,66 1108,66 1308,66 1508,66 1708,66 1908,66 408,266 1808,266 2008,266 2208,266 108,466 508,466 1508,466 1908,466 2108,466 850,620 208,666 408,666 1208,666 1408,666 1608,666 108,866 508,866 908,866 1308,866 1508,866 1708,866 808,1066 2208,1066 1430,1200 1245,1235 1388,1240 108,1266 508,1266 708,1266 908,1266 1205,1275 1245,1275 1285,1275 1205,1315 1285,1315 1690,1410 1735,1410 1585,1425 1640,1425 1450,1455 1495,1455 1540,1455 608,1466 808,1466 1008,1466 1408,1466 1608,1466 1808,1466 2208,1466 108,1666 508,1666 708,1666 908,1666 1108,1666 1308,1666 1508,1666 1708,1666 208,1866 2208,1866 108,2066 308,2066 508,2066 708,2066 908,2066 1108,2066 1308,2066 1508,2066 1708,2066 1908,2066 2108,2066 208,2266 408,2266 608,2266 808,2266 1008,2266 1408,2266 1608,2266 1808,2266 2008,2266 2208,2266 108,2466 308,2466 508,2466 708,2466 908,2466 1108,2466 1308,2466 1508,2466 1708,2466 1908,2466 2108,2466 208,2666 408,2666 608,2666 808,2666 1008,2666 1208,2666 1408,2666 1608,2666 1808,2666 2008,2666 2208,2666 108,2866 308,2866 508,2866 708,2866 908,2866 1108,2866 1308,2866 1508,2866 1708,2866 1908,2866 2108,2866 208,3066 408,3066 608,3066 808,3066 1008,3066 1208,3066 1408,3066 1608,3066 1808,3066 2008,3066 2208,3066 108,3266 308,3266 1108,3266 1308,3266 1508,3266 1708,3266 1908,3266 2108,3266 208,3466 408,3466 608,3466 808,3466 1008,3466 1208,3466 1408,3466 1608,3466 1808,3466 2008,3466 2208,3466
  other v3: 1287.03,1200 1330.33,1200
LS_INT: J2.7 U3.6 | length 649.7
  Layer 1 - Top Layer w8: U3.6@1632.7,1057.4 v1(1680,1057.4)
  Layer 4 - Bottom Layer w8: v1(1680,1057.4) 1845.08,1057.4 1882.23,1094.56 1882.23,1380.54 J2.7@1952.09,1450.39
NetBT1_1: BT1.1 Q1.3
NetC1_2: C1.2 R1.1 R4.2 U1.6 | length 176
  Layer 1 - Top Layer w20: R4.2@610,841.38 R1.1@610,778.62 C1.2@655,778.62 656.38,780 U1.6@722.72,780
NetC2_2: C2.2 R18.1 U1.8 | length 114.8
  Layer 1 - Top Layer w20: R18.1@718.5,570 726.38,577.87 C2.2@726.38,620 726.38,676.34 U1.8@722.72,680
NetC3_1: C3.1 R5.2 U1.3 | length 133.2
  Layer 1 - Top Layer w20: U1.3@937.28,780 1003.5,780 C3.1@1010,773.5 1013.5,770 R5.2@1066.38,770
NetC4_1: C4.1 C5.1 C6.1 C7.1 C8.1 J3.1 Q2.2
NetC9_1: C9.1 L1.1 R9.2 U4.3 U4.4 | length 185.2
  Layer 1 - Top Layer w8: U4.4@1334.27,1238.39 1334.27,1254.27 v1(1355,1275)
  Layer 4 - Bottom Layer w8: v1(1355,1135) v1(1355,1275)
NetC10_1: C10.1 R8.2 U3.4 U3.5
NetC11_1: C11.1 R12.1 U7.2 | length 184.6
  Layer 1 - Top Layer w8: U7.2@613.86,505.43 613.86,456.14 630,440 650,440
  Layer 1 - Top Layer w20: 650,440 688.7,440 C11.1@689.09,440.39 731.22,440.39 R12.1@739.09,448.27
NetC12_1: C12.1 R10.1 U7.9 U7.10
NetC13_1: C13.1 R14.2 R15.1 U6.6 | length 215.4
  Layer 1 - Top Layer w15: R15.1@780.67,506.77 788.82,498.62 R14.2@860,498.62 912.87,498.62 C13.1@915,496.5 920.43,501.93 U6.6@989.53,501.93
NetC14_1: C14.1 U6.5 | length 67.1
  Layer 1 - Top Layer w20: U6.5@989.53,551.93 989.53,588.15 C14.1@1011.38,610
NetC15_1: C15.1 R14.1 | length 73
  Layer 1 - Top Layer w15: C15.1@844.17,384.96 860,400.79 R14.1@860,451.38
NetC16_1: C16.1 R16.2 U7.3 | length 134.3
  Layer 1 - Top Layer w8: U7.3@594.17,505.43 594.17,550.28 C16.1@615.67,571.77
  Layer 1 - Top Layer w20: R16.2@609.17,628.15 609.17,578.27 C16.1@615.67,571.77
NetC16_2: C16.2 R17.2 U7.4 | length 125.3
  Layer 1 - Top Layer w8: C16.2@552.68,571.77 574.49,549.96 U7.4@574.49,505.43
  Layer 1 - Top Layer w20: C16.2@559.17,578.27 R17.2@559.17,628.15
NetC17_1: C17.1 R13.2 U6.2 | length 130.6
  Layer 1 - Top Layer w20: U6.2@1204.09,451.93 1332.56,451.93 R13.2@1334.09,453.46
NetL1_2: L1.2 U4.1
NetQ1_2: Q1.2 Q2.3
NetR2_1: R2.1 R5.1 R6.2 | length 90
  Layer 1 - Top Layer w20: R2.1@1113.62,725 R6.2@1113.62,815
NetR3_1: R3.1 U1.1 U1.2 | length 691.4
  Layer 1 - Top Layer w20: v1(565,797.83) R3.1@565,841.38 ; v2(937.28,610) U1.1@937.28,680 U1.2@937.28,730
  Layer 4 - Bottom Layer w20: v1(565,797.83) 592.83,770 910,770 937.28,742.72 v2(937.28,610)
NetR3_2: R3.2 R4.1 R7.1 U2.2 | length 306.5
  Layer 1 - Top Layer w20: R3.2@565,888.62 R4.1@610,888.62 R4.1@610.83,889.45 ; U2.2@587.29,1094.29 610.83,1070.75 v2(610.83,948) R4.1@610.83,889.45 ; R7.1@656.38,890 611.38,890 R4.1@610.83,889.45
NetR7_2: R7.2 U1.5 U2.3 | length 283.5
  Layer 1 - Top Layer w20: U1.5@702.72,830 U1.5@703.62,830.91 ; R7.2@703.62,890 722.72,870.91 U1.5@722.72,830 ; R7.2@704.45,890 v2(704.45,948) 704.45,1070.02 U2.3@728.71,1094.29
NetR9_1: R9.1 U3.1
NetR15_2: R15.2 U7.1 | length 79.7
  Layer 1 - Top Layer w15: U7.1@638,506.77 R15.2@717.68,506.77
SENSOR_OUT: C1.1 R1.2 R16.1 U1.7 | length 234.6
  Layer 1 - Top Layer w20: v2(545,731.38) R1.2@610,731.38 ; R16.1@609.17,675.39 610,676.22 R1.2@610,731.38 ; U1.7@722.72,730 611.38,730 R1.2@610,731.38
SPI_CLK: J1.13 U7.8 | length 1257.7
  Layer 1 - Top Layer w8: U7.8@594.17,338.11 v1(594.17,390)
  Layer 4 - Bottom Layer w8: J1.13@251.3,1150.39 200.39,1150.39 175,1125 175,450 210,415 569.17,415 v1(594.17,390)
